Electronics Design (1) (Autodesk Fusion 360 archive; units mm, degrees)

design "PCB"
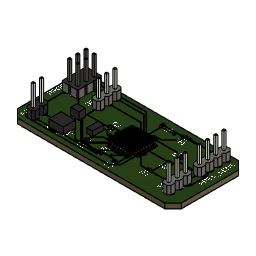
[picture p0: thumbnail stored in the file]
sketch "Outline" plane through (0, 0, 0) normal (0, 0, 1) x axis (1, 0, 0)
  line L1 (2.54, 0) -> (0, 2.54)
  line L2 (48.26, 0) -> (2.54, 0)
  line L3 (50.8, 2.54) -> (48.26, 0)
  line L4 (50.8, 20.32) -> (50.8, 2.54)
  line L5 (48.26, 22.86) -> (50.8, 20.32)
  line L6 (2.54, 22.86) -> (48.26, 22.86)
  line L7 (0, 20.32) -> (2.54, 22.86)
  line L8 (0, 2.54) -> (0, 20.32)
canvas "Canvas1" bodies "Board"
canvas "Canvas2" bodies "Board"
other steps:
base_feature "Base Feature1"
base_feature "Base Feature1"
base_feature "Base Feature1"
base_feature "Base Feature1"
extrude "Extrude1" sketch "Outline" blind 1.5 bodies "Board"
pcbextrude "PCBExtrude1"
pcbextrude "PCBExtrude1"
pcbextrude "PCBExtrude1"
pcbextrude "PCBExtrude1"
base_feature "Base Feature1"
base_feature "Base Feature1"
base_feature "Base Feature1"
box_primitive "BoxPrimitive1" DistanceX 3.5 DistanceY 1.8 DistanceZ 1.4857 OffsetDistanceX 0 OffsetDistanceY 0
box_primitive "BoxPrimitive1" DistanceX 2 DistanceY 2.55 DistanceZ 2.2281 OffsetDistanceX 0 OffsetDistanceY 0
box_primitive "BoxPrimitive1" DistanceX 4.4224 DistanceY 3.7846 DistanceZ 2.16 OffsetDistanceX 0 OffsetDistanceY 0
pcbextrude "PCBExtrude1"
pcbextrude "PCBExtrude2" bodies "CopperHoles"
create_component "CreateComponent1"
create_component "CreateComponent2"
create_component "CreateComponent3"
create_component "CreateComponent4"
create_component "CreateComponent5"
create_component "CreateComponent6"
create_component "CreateComponent1"
create_component "CreateComponent6"
create_component "CreateComponent7"
create_component "CreateComponent8"
create_component "CreateComponent9"
create_component "CreateComponent10"
as_built_joint "As-built1"
create_component "CreateComponent14"
create_component "CreateComponent15"
create_component "CreateComponent16"
create_component "CreateComponent17"
named bodies: "Board", "CopperHoles"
